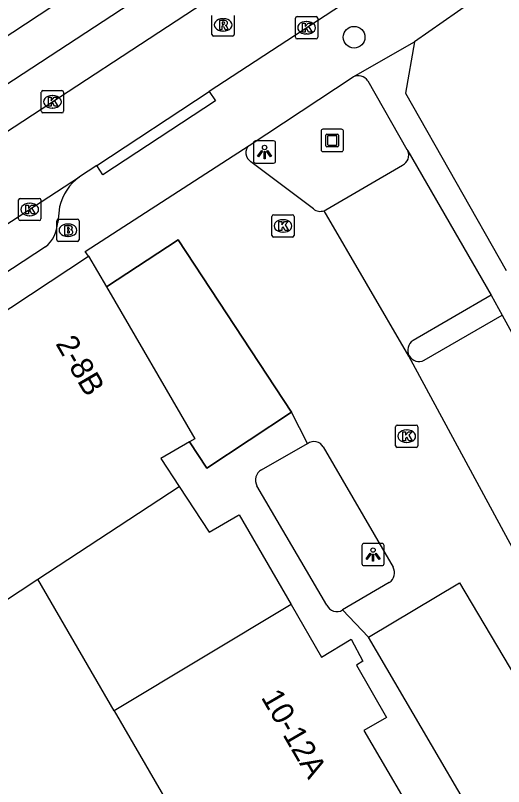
# Model space of a CAD drawing. Extents: x 161801 to 162379, y 382315 to 382832.
# Drawn here: x 162101.65 to 162123.59, y 382570.14 to 382604.76 of the extents above; entities that cross this region are included whole.
import ezdxf

# ---------------------------------------------------------------- set-up
doc = ezdxf.new("R2010")
doc.units = 0
for name, color, linetype in [('IMGEO_Boom', 7, 'Continuous'), ('IMGEO_Brandkraan', 7, 'Continuous'), ('IMGEO_Kolk', 7, 'Continuous'), ('IMGEO_Kunstobject', 7, 'Continuous'), ('IMGEO_Lichtpunt', 7, 'Continuous'), ('IMGEO_Pand', 7, 'Continuous'), ('IMGEO_Pand_nummerreeks', 7, 'Continuous'), ('IMGEO_Pand_overbouw', 7, 'Continuous'), ('IMGEO_Parkeervlak_open', 7, 'Continuous'), ('IMGEO_Rijbaan_lokaal_open', 7, 'Continuous'), ('IMGEO_Rioolput', 7, 'Continuous'), ('IMGEO_Voetpad_open', 7, 'Continuous'), ('IMGEO_Woonerf_open', 7, 'Continuous')]:
    doc.layers.add(name, color=color, linetype=linetype)

msp = doc.modelspace()

# ---------------------------------------------------------------- linework, layer by layer
at = {"layer": 'IMGEO_Boom'}
msp.add_circle((162116.868, 382603.78), 0.489, dxfattribs=at)
at = {"layer": 'IMGEO_Brandkraan'}
for p, q in [((162103.507, 382594.688), (162103.507, 382595.54)), ((162103.582, 382595.614), (162104.434, 382595.614)), ((162104.508, 382595.54), (162104.508, 382594.688)), ((162103.995, 382595.394), (162104.02, 382595.394)), ((162104.018, 382594.834), (162103.993, 382594.834)), ((162104.434, 382594.614), (162103.582, 382594.614))]:
    msp.add_line(p, q, dxfattribs=at)
for points in [[(162103.507, 382594.688), (162103.507, 382595.54)], [(162103.582, 382595.614), (162104.434, 382595.614)], [(162104.508, 382595.54), (162104.508, 382594.688)], [(162103.855, 382595.314), (162103.855, 382594.914), (162104.068, 382594.914)], [(162104.086, 382595.314), (162103.855, 382595.314)], [(162104.034, 382595.233), (162103.98, 382595.233), (162103.98, 382595.157)], [(162103.98, 382595.157), (162104.033, 382595.157)], [(162104.042, 382595.081), (162103.98, 382595.081), (162103.98, 382595)], [(162103.98, 382595), (162104.042, 382595)], [(162104.434, 382594.614), (162103.582, 382594.614)]]:
    msp.add_lwpolyline(points, dxfattribs=at)
for centre, radius, start, end in [((162103.584, 382595.538), 0.0765, 91.552, 178.448), ((162103.584, 382595.538), 0.0765, 91.552, 178.448), ((162104.432, 382595.538), 0.0765, 1.552, 88.448), ((162104.432, 382595.538), 0.0765, 1.552, 88.448), ((162104.035, 382595.195), 0.0379, 267.8285, 90.9355), ((162104.09, 382595.169), 0.145, 59.4692, 91.5367), ((162104.115, 382595.216), 0.0922, 285.5137, 58.1501), ((162104.043, 382595.04), 0.0404, 269.8759, 90.5077), ((162104.074, 382595.165), 0.251, 268.6676, 293.5347), ((162104.12, 382595.024), 0.105, 301.3115, 78.989), ((162103.584, 382594.69), 0.0765, 181.552, 268.448), ((162103.584, 382594.69), 0.0765, 181.552, 268.448), ((162104.432, 382594.69), 0.0765, 271.552, 358.448), ((162104.432, 382594.69), 0.0765, 271.552, 358.448)]:
    msp.add_arc(centre, radius, start, end, dxfattribs=at)
for centre, major_axis, ratio, start_param, end_param in [((162103.994, 382595.114), (-0.387, 0.002), 0.722429, 4.712389, 7.853982), ((162104.019, 382595.114), (-0.39, 0.002), 0.717154, 1.570796, 4.712389)]:
    msp.add_ellipse(centre, major_axis=major_axis, ratio=ratio, start_param=start_param, end_param=end_param, dxfattribs=at)
at = {"layer": 'IMGEO_Kolk'}
for p, q in [((162114.232, 382603.78), (162114.232, 382604.632)), ((162114.307, 382604.706), (162115.159, 382604.706)), ((162114.72, 382604.486), (162114.745, 382604.486)), ((162115.233, 382604.632), (162115.233, 382603.78)), ((162114.743, 382603.926), (162114.718, 382603.926)), ((162115.159, 382603.706), (162114.307, 382603.706)), ((162102.886, 382601.382), (162103.738, 382601.382)), ((162102.811, 382600.456), (162102.811, 382601.308)), ((162103.299, 382601.162), (162103.324, 382601.162)), ((162103.812, 382601.308), (162103.812, 382600.456)), ((162103.738, 382600.382), (162102.886, 382600.382)), ((162103.322, 382600.602), (162103.297, 382600.602)), ((162101.864, 382596.546), (162102.716, 382596.546)), ((162101.789, 382595.62), (162101.789, 382596.472)), ((162102.277, 382596.326), (162102.302, 382596.326)), ((162102.79, 382596.472), (162102.79, 382595.62)), ((162102.716, 382595.546), (162101.864, 382595.546)), ((162102.3, 382595.766), (162102.275, 382595.766)), ((162113.172, 382594.881), (162113.172, 382595.733)), ((162113.247, 382595.807), (162114.099, 382595.807)), ((162113.66, 382595.587), (162113.685, 382595.587)), ((162114.173, 382595.733), (162114.173, 382594.881)), ((162114.099, 382594.807), (162113.247, 382594.807)), ((162113.683, 382595.027), (162113.658, 382595.027)), ((162118.733, 382585.44), (162118.733, 382586.292)), ((162118.808, 382586.366), (162119.66, 382586.366)), ((162119.221, 382586.146), (162119.246, 382586.146)), ((162119.734, 382586.292), (162119.734, 382585.44)), ((162119.244, 382585.586), (162119.219, 382585.586)), ((162119.66, 382585.366), (162118.808, 382585.366))]:
    msp.add_line(p, q, dxfattribs=at)
for points in [[(162114.232, 382603.78), (162114.232, 382604.632)], [(162114.307, 382604.706), (162115.159, 382604.706)], [(162115.233, 382604.632), (162115.233, 382603.78)], [(162114.553, 382604.406), (162114.676, 382604.406), (162114.676, 382604.255), (162114.806, 382604.406), (162114.97, 382604.406), (162114.824, 382604.255), (162114.977, 382604.006), (162114.825, 382604.006), (162114.74, 382604.17), (162114.676, 382604.103), (162114.676, 382604.006), (162114.553, 382604.006), (162114.553, 382604.406)], [(162115.159, 382603.706), (162114.307, 382603.706)], [(162102.886, 382601.382), (162103.738, 382601.382)], [(162102.811, 382600.456), (162102.811, 382601.308)], [(162103.132, 382601.082), (162103.255, 382601.082), (162103.255, 382600.931), (162103.385, 382601.082), (162103.549, 382601.082), (162103.403, 382600.931), (162103.556, 382600.682), (162103.404, 382600.682), (162103.319, 382600.846), (162103.255, 382600.779), (162103.255, 382600.682), (162103.132, 382600.682), (162103.132, 382601.082)], [(162103.812, 382601.308), (162103.812, 382600.456)], [(162103.738, 382600.382), (162102.886, 382600.382)], [(162101.864, 382596.546), (162102.716, 382596.546)], [(162101.789, 382595.62), (162101.789, 382596.472)], [(162102.11, 382596.246), (162102.233, 382596.246), (162102.233, 382596.095), (162102.363, 382596.246), (162102.527, 382596.246), (162102.381, 382596.095), (162102.534, 382595.846), (162102.382, 382595.846), (162102.297, 382596.01), (162102.233, 382595.943), (162102.233, 382595.846), (162102.11, 382595.846), (162102.11, 382596.246)], [(162102.79, 382596.472), (162102.79, 382595.62)], [(162102.716, 382595.546), (162101.864, 382595.546)], [(162113.172, 382594.881), (162113.172, 382595.733)], [(162113.247, 382595.807), (162114.099, 382595.807)], [(162113.493, 382595.507), (162113.616, 382595.507), (162113.616, 382595.356), (162113.746, 382595.507), (162113.91, 382595.507), (162113.764, 382595.356), (162113.917, 382595.107), (162113.765, 382595.107), (162113.68, 382595.271), (162113.616, 382595.204), (162113.616, 382595.107), (162113.493, 382595.107), (162113.493, 382595.507)], [(162114.173, 382595.733), (162114.173, 382594.881)], [(162114.099, 382594.807), (162113.247, 382594.807)], [(162118.733, 382585.44), (162118.733, 382586.292)], [(162118.808, 382586.366), (162119.66, 382586.366)], [(162119.734, 382586.292), (162119.734, 382585.44)], [(162119.054, 382586.066), (162119.177, 382586.066), (162119.177, 382585.915), (162119.307, 382586.066), (162119.471, 382586.066), (162119.325, 382585.915), (162119.478, 382585.666), (162119.326, 382585.666), (162119.241, 382585.83), (162119.177, 382585.763), (162119.177, 382585.666), (162119.054, 382585.666), (162119.054, 382586.066)], [(162119.66, 382585.366), (162118.808, 382585.366)]]:
    msp.add_lwpolyline(points, dxfattribs=at)
for centre, start, end in [((162114.309, 382604.63), 91.552, 178.448), ((162114.309, 382604.63), 91.552, 178.448), ((162115.157, 382604.63), 1.552, 88.448), ((162115.157, 382604.63), 1.552, 88.448), ((162114.309, 382603.782), 181.552, 268.448), ((162114.309, 382603.782), 181.552, 268.448), ((162115.157, 382603.782), 271.552, 358.448), ((162115.157, 382603.782), 271.552, 358.448), ((162102.888, 382601.306), 91.552, 178.448), ((162102.888, 382601.306), 91.552, 178.448), ((162103.736, 382601.306), 1.552, 88.448), ((162103.736, 382601.306), 1.552, 88.448), ((162102.888, 382600.458), 181.552, 268.448), ((162102.888, 382600.458), 181.552, 268.448), ((162103.736, 382600.458), 271.552, 358.448), ((162103.736, 382600.458), 271.552, 358.448), ((162101.866, 382596.47), 91.552, 178.448), ((162101.866, 382596.47), 91.552, 178.448), ((162102.714, 382596.47), 1.552, 88.448), ((162102.714, 382596.47), 1.552, 88.448), ((162101.866, 382595.622), 181.552, 268.448), ((162101.866, 382595.622), 181.552, 268.448), ((162102.714, 382595.622), 271.552, 358.448), ((162102.714, 382595.622), 271.552, 358.448), ((162113.249, 382595.731), 91.552, 178.448), ((162113.249, 382595.731), 91.552, 178.448), ((162114.097, 382595.731), 1.552, 88.448), ((162114.097, 382595.731), 1.552, 88.448), ((162113.249, 382594.883), 181.552, 268.448), ((162113.249, 382594.883), 181.552, 268.448), ((162114.097, 382594.883), 271.552, 358.448), ((162114.097, 382594.883), 271.552, 358.448), ((162118.81, 382586.29), 91.552, 178.448), ((162118.81, 382586.29), 91.552, 178.448), ((162119.658, 382586.29), 1.552, 88.448), ((162119.658, 382586.29), 1.552, 88.448), ((162118.81, 382585.442), 181.552, 268.448), ((162118.81, 382585.442), 181.552, 268.448), ((162119.658, 382585.442), 271.552, 358.448), ((162119.658, 382585.442), 271.552, 358.448)]:
    msp.add_arc(centre, 0.0765, start, end, dxfattribs=at)
for centre, major_axis, ratio, start_param, end_param in [((162114.719, 382604.206), (-0.387, 0.002), 0.722429, 4.712389, 7.853982), ((162114.744, 382604.206), (-0.39, 0.002), 0.717154, 1.570796, 4.712389), ((162103.298, 382600.882), (-0.387, 0.002), 0.722429, 4.712389, 7.853982), ((162103.323, 382600.882), (-0.39, 0.002), 0.717154, 1.570796, 4.712389), ((162102.276, 382596.046), (-0.387, 0.002), 0.722429, 4.712389, 7.853982), ((162102.301, 382596.046), (-0.39, 0.002), 0.717154, 1.570796, 4.712389), ((162113.659, 382595.307), (-0.387, 0.002), 0.722429, 4.712389, 7.853982), ((162113.684, 382595.307), (-0.39, 0.002), 0.717154, 1.570796, 4.712389), ((162119.22, 382585.866), (-0.387, 0.002), 0.722429, 4.712389, 7.853982), ((162119.245, 382585.866), (-0.39, 0.002), 0.717154, 1.570796, 4.712389)]:
    msp.add_ellipse(centre, major_axis=major_axis, ratio=ratio, start_param=start_param, end_param=end_param, dxfattribs=at)
at = {"layer": 'IMGEO_Kunstobject'}
for p, q in [((162116.301, 382599.646), (162115.46, 382599.646)), ((162116.301, 382599.646), (162115.46, 382599.646)), ((162115.385, 382599.562), (162115.385, 382598.721)), ((162115.385, 382599.562), (162115.385, 382598.721)), ((162115.599, 382598.91), (162115.599, 382599.384)), ((162115.649, 382599.434), (162116.123, 382599.434)), ((162115.679, 382599.334), (162115.679, 382598.96)), ((162116.073, 382599.354), (162115.699, 382599.354)), ((162116.093, 382598.96), (162116.093, 382599.334)), ((162116.173, 382599.384), (162116.173, 382598.91)), ((162116.385, 382598.73), (162116.385, 382599.571)), ((162116.385, 382598.73), (162116.385, 382599.571)), ((162115.469, 382598.646), (162116.31, 382598.646)), ((162115.469, 382598.646), (162116.31, 382598.646)), ((162116.123, 382598.86), (162115.649, 382598.86)), ((162115.699, 382598.94), (162116.073, 382598.94))]:
    msp.add_line(p, q, dxfattribs=at)
for centre, radius, start, end in [((162115.463, 382599.568), 0.0779, 92.4484, 184.2845), ((162115.463, 382599.568), 0.0779, 92.4484, 184.2845), ((162116.307, 382599.568), 0.0779, 2.4484, 94.2845), ((162116.307, 382599.568), 0.0779, 2.4484, 94.2845), ((162115.649, 382599.384), 0.05, 90, 180), ((162115.699, 382599.334), 0.02, 90, 180), ((162116.073, 382599.334), 0.02, 360, 90), ((162116.123, 382599.384), 0.05, 360, 90), ((162115.699, 382598.96), 0.02, 180, 270), ((162116.073, 382598.96), 0.02, 270, 0), ((162115.463, 382598.724), 0.0779, 182.4484, 274.2845), ((162115.463, 382598.724), 0.0779, 182.4484, 274.2845), ((162115.649, 382598.91), 0.05, 180, 270), ((162116.123, 382598.91), 0.05, 270, 0), ((162116.307, 382598.724), 0.0779, 272.4484, 4.2845), ((162116.307, 382598.724), 0.0779, 272.4484, 4.2845)]:
    msp.add_arc(centre, radius, start, end, dxfattribs=at)
at = {"layer": 'IMGEO_Lichtpunt'}
for p, q in [((162112.345, 382599.033), (162112.345, 382598.226)), ((162112.345, 382599.033), (162112.345, 382598.226)), ((162113.247, 382599.128), (162112.439, 382599.128)), ((162113.247, 382599.128), (162112.439, 382599.128)), ((162113.341, 382598.226), (162113.341, 382599.033)), ((162113.341, 382598.226), (162113.341, 382599.033)), ((162112.439, 382598.132), (162113.247, 382598.132)), ((162112.439, 382598.132), (162113.247, 382598.132)), ((162117.222, 382580.956), (162117.222, 382580.149)), ((162117.222, 382580.956), (162117.222, 382580.149)), ((162118.124, 382581.051), (162117.316, 382581.051)), ((162118.124, 382581.051), (162117.316, 382581.051)), ((162118.218, 382580.149), (162118.218, 382580.956)), ((162118.218, 382580.149), (162118.218, 382580.956)), ((162117.316, 382580.055), (162118.124, 382580.055)), ((162117.316, 382580.055), (162118.124, 382580.055))]:
    msp.add_line(p, q, dxfattribs=at)
for points in [[(162112.719, 382598.697), (162112.758, 382598.669), (162112.57, 382598.407), (162112.532, 382598.434), (162112.719, 382598.697)], [(162112.821, 382598.649), (162112.868, 382598.649), (162112.868, 382598.327), (162112.821, 382598.327), (162112.821, 382598.649)], [(162112.931, 382598.669), (162112.969, 382598.696), (162113.156, 382598.434), (162113.117, 382598.406), (162112.931, 382598.669)], [(162117.596, 382580.62), (162117.635, 382580.592), (162117.447, 382580.33), (162117.409, 382580.357), (162117.596, 382580.62)], [(162117.808, 382580.592), (162117.846, 382580.619), (162118.033, 382580.357), (162117.994, 382580.329), (162117.808, 382580.592)], [(162117.698, 382580.572), (162117.745, 382580.572), (162117.745, 382580.25), (162117.698, 382580.25), (162117.698, 382580.572)]]:
    msp.add_lwpolyline(points, dxfattribs=at)
for centre in [(162112.844, 382598.831), (162117.721, 382580.754)]:
    msp.add_circle(centre, 0.0994, dxfattribs=at)
for centre, start, end in [((162112.439, 382599.033), 90, 180), ((162112.439, 382599.033), 90, 180), ((162113.247, 382599.033), 0, 90), ((162113.247, 382599.033), 0, 90), ((162112.439, 382598.226), 180, 270), ((162112.439, 382598.226), 180, 270), ((162113.247, 382598.226), 270, 0), ((162113.247, 382598.226), 270, 360), ((162117.316, 382580.956), 90, 180), ((162117.316, 382580.956), 90, 180), ((162118.124, 382580.956), 0, 90), ((162118.124, 382580.956), 0, 90), ((162117.316, 382580.149), 180, 270), ((162117.316, 382580.149), 180, 270), ((162118.124, 382580.149), 270, 0), ((162118.124, 382580.149), 270, 360)]:
    msp.add_arc(centre, 0.0946, start, end, dxfattribs=at)
at = {"layer": 'IMGEO_Pand'}
for points in [[(162112.221, 382611.038), (162100.902, 382603.585)], [(162123.564, 382606.422), (162123.441, 382606.277), (162119.59, 382603.578)], [(162119.59, 382603.578), (162119.172, 382601.276), (162123.71, 382593.31)], [(162093.517, 382584.575), (162100.557, 382589.214), (162099.697, 382590.512), (162104.937, 382593.957)], [(162104.937, 382593.957), (162105.744, 382592.57)], [(162105.744, 382592.57), (162109.71, 382585.755), (162109.471, 382585.616)], [(162109.471, 382585.616), (162108.181, 382584.865), (162108.999, 382583.616)], [(162102.649, 382579.449), (162108.999, 382583.616)], [(162108.999, 382583.616), (162110.348, 382581.555), (162111.65, 382582.313), (162111.696, 382582.339), (162114.042, 382578.304)], [(162098.622, 382576.803), (162102.649, 382579.449)], [(162106.08, 382573.541), (162102.649, 382579.449)], [(162114.042, 382578.304), (162106.08, 382573.541)], [(162114.042, 382578.304), (162115.409, 382575.952), (162116.738, 382576.747), (162117.261, 382575.769), (162116.97, 382575.589), (162118.318, 382573.243), (162117.306, 382572.656), (162120.071, 382567.925)], [(162106.08, 382573.541), (162112.045, 382563.269)]]:
    msp.add_lwpolyline(points, dxfattribs=at)
at = {"layer": 'IMGEO_Pand_overbouw'}
msp.add_lwpolyline([(162109.471, 382585.616), (162110.249, 382584.437), (162114.048, 382586.943), (162108.961, 382594.691), (162105.744, 382592.57), (162109.71, 382585.755)], close=True, dxfattribs=at)
at = {"layer": 'IMGEO_Parkeervlak_open'}
for points in [[(162115.602, 382596.03), (162119.046, 382598.041)], [(162124.379, 382581.034), (162123.981, 382580.856), (162119.326, 382589.466), (162115.517, 382595.99)], [(162123.035, 382592.201), (162119.517, 382590.158)], [(162120.015, 382589.276), (162123.529, 382591.302)], [(162117.511, 382576.849), (162121.605, 382579.284), (162126.691, 382570.732), (162129.711, 382565.654)]]:
    msp.add_lwpolyline(points, dxfattribs=at)
for centre, radius, start, end in [((162118.851, 382598.471), 0.472, 294.4158, 25.8207), ((162115.328, 382596.503), 0.546, 290.2696, 300.1327), ((162119.785, 382589.728), 0.507, 121.9304, 296.97)]:
    msp.add_arc(centre, radius, start, end, dxfattribs=at)
at = {"layer": 'IMGEO_Rijbaan_lokaal_open'}
for points in [[(162111.73, 382606.38), (162087.354, 382590.455)], [(162117.507, 382605.989), (162116.651, 382605.458), (162114.877, 382604.291), (162110.359, 382601.34)], [(162105.299, 382598.022), (162110.359, 382601.34)], [(162105.299, 382598.022), (162104.523, 382597.511)], [(162092.248, 382589.524), (162104.523, 382597.511)]]:
    msp.add_lwpolyline(points, dxfattribs=at)
at = {"layer": 'IMGEO_Rioolput'}
for p, q in [((162110.481, 382603.907), (162110.481, 382604.759)), ((162110.969, 382604.613), (162110.994, 382604.613)), ((162111.482, 382604.759), (162111.482, 382603.907)), ((162111.408, 382603.833), (162110.556, 382603.833)), ((162110.992, 382604.053), (162110.967, 382604.053))]:
    msp.add_line(p, q, dxfattribs=at)
for points in [[(162110.481, 382603.907), (162110.481, 382604.759)], [(162111.07, 382604.531), (162110.818, 382604.533), (162110.818, 382604.133)], [(162111.482, 382604.759), (162111.482, 382603.907)], [(162110.818, 382604.133), (162110.942, 382604.133), (162110.942, 382604.295), (162110.953, 382604.295)], [(162110.996, 382604.452), (162110.942, 382604.452), (162110.942, 382604.371)], [(162110.942, 382604.371), (162110.994, 382604.371)], [(162111, 382604.266), (162111.071, 382604.133), (162111.211, 382604.133), (162111.146, 382604.259)], [(162111.408, 382603.833), (162110.556, 382603.833)]]:
    msp.add_lwpolyline(points, dxfattribs=at)
for centre, radius, start, end in [((162111.069, 382604.421), 0.109, 350.3612, 89.416), ((162110.952, 382604.242), 0.0533, 26.0293, 88.6989), ((162110.978, 382604.56), 0.19, 274.7715, 282.9687), ((162111.002, 382604.356), 0.0964, 77.0061, 93.1865), ((162111.016, 382604.413), 0.0378, 276.6634, 79.6772), ((162111.067, 382604.421), 0.112, 277.5842, 350.9817), ((162111.051, 382604.206), 0.108, 29.5134, 73.7905), ((162110.558, 382603.909), 0.0765, 181.552, 268.448), ((162110.558, 382603.909), 0.0765, 181.552, 268.448), ((162111.406, 382603.909), 0.0765, 271.552, 358.448), ((162111.406, 382603.909), 0.0765, 271.552, 358.448)]:
    msp.add_arc(centre, radius, start, end, dxfattribs=at)
for centre, major_axis, ratio, start_param, end_param in [((162110.968, 382604.333), (-0.387, 0.002), 0.722429, 4.712389, 7.853982), ((162110.993, 382604.333), (-0.39, 0.002), 0.717154, 1.570796, 4.712389)]:
    msp.add_ellipse(centre, major_axis=major_axis, ratio=ratio, start_param=start_param, end_param=end_param, dxfattribs=at)
at = {"layer": 'IMGEO_Voetpad_open'}
for points in [[(162088.725, 382593.485), (162108.41, 382606.351)], [(162116.822, 382602.004), (162119.59, 382603.578)], [(162112.146, 382598.926), (162116.822, 382602.004)], [(162117.48, 382601.824), (162119.24, 382598.739), (162119.276, 382598.677)], [(162110.359, 382601.34), (162110.633, 382600.922), (162105.573, 382597.604), (162105.299, 382598.022)], [(162104.937, 382593.957), (162104.785, 382594.155), (162112.146, 382598.926)], [(162119.276, 382598.677), (162123.035, 382592.201)], [(162103.632, 382596.166), (162103.546, 382595.455)], [(162105.744, 382592.57), (162108.961, 382594.691), (162114.048, 382586.943)], [(162103.003, 382594.362), (162095.567, 382589.499)], [(162123.035, 382592.201), (162123.529, 382591.302)], [(162123.529, 382591.302), (162128.008, 382583.149)], [(162114.048, 382586.943), (162110.249, 382584.437), (162109.471, 382585.616)], [(162114.781, 382585.532), (162114.048, 382586.943)], [(162112.703, 382584.36), (162114.781, 382585.532)], [(162115.645, 382578.277), (162112.504, 382583.634)], [(162117.511, 382576.849), (162116.346, 382578.064)], [(162148.876, 382532.598), (162145.486, 382538.236), (162144.332, 382540.219), (162140.243, 382537.843), (162136.179, 382544.834), (162124.722, 382564.546), (162117.511, 382576.849)]]:
    msp.add_lwpolyline(points, dxfattribs=at)
for centre, radius, start, end in [((162117.043, 382601.519), 0.533, 34.8953, 114.5061), ((162105.849, 382595.665), 2.273, 125.6891, 167.2657), ((162102.006, 382595.539), 1.542, 310.2687, 356.8952), ((162112.983, 382583.893), 0.545, 120.9788, 208.3641), ((162116.086, 382578.47), 0.482, 203.5887, 302.6084)]:
    msp.add_arc(centre, radius, start, end, dxfattribs=at)
at = {"layer": 'IMGEO_Woonerf_open'}
for points in [[(162115.044, 382596.07), (162112.233, 382598.192)], [(162115.484, 382585.384), (162118.619, 382579.986)], [(162118.448, 382579.296), (162116.346, 382578.064)]]:
    msp.add_lwpolyline(points, dxfattribs=at)
for centre, radius, start, end in [((162112.467, 382598.592), 0.463, 133.8688, 239.6505), ((162115.352, 382596.455), 0.493, 231.3095, 289.4909), ((162115.069, 382585.158), 0.472, 28.6017, 127.621), ((162118.166, 382579.732), 0.519, 302.8968, 29.2652)]:
    msp.add_arc(centre, radius, start, end, dxfattribs=at)

# ---------------------------------------------------------------- texts
at = {"layer": 'IMGEO_Pand_nummerreeks'}
for s, rotation, p in [('2-8B', 300.1965, (162103.43, 382590.024)), ('10-12A', 300.1524, (162112.665, 382574.144))]:
    msp.add_text(s, height=1, rotation=rotation, dxfattribs=at).set_placement(p)

doc.saveas('drawing.dxf')
